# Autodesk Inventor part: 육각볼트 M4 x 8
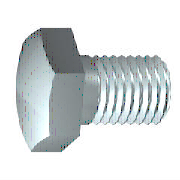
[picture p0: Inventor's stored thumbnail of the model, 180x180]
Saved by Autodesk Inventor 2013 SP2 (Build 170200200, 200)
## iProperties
Created: 2012-02
Part Number: 육각볼트 M4 x 8
Material: 강철, 연강
Description: 6각 머리 나사
Document SubType Name: Modeling
Standard: ISO 4017
Designer: mduedu
Standard Revision: Third edition 1999-08-15
Standards Organization: ISO
Language: ko-KR
Size Designation: M4 x 10
Categories: <MemberInstance><Categories><Category DisplayName="조임쇠" InternalName="e4da775c-781d-43d5-af7c-5136215cf5a6" Mnemonic="FSTN"><Category DisplayName="볼트" InternalN
Density: 7.86 g/cm^3
IsCustomPart: 0
Author: mduedu
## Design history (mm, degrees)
sketch "스케치1"
  geometry: L1 (0, 3.015)-(0, 2); L2 (1.75, 2)-(8, 2); L3 (8, 2)-(8, 0); L4 (8, 0)-(-0.4, 0); L5 (-2.08, 0)-(9.68, 0) reference; L6 (-0.4, 0)-(-0.4, 3.015); L7 (-0.4, 3.015)-(0, 3.015); L8 (1.75, 2)-(1.32, 2); L9 (1.32, 2)-(0, 2); L10 (0, -0.603)-(0, 3.618) reference
  constraints: 16 end point, 2 collinear, 2 perpendicular, 1 parallel
  dimensions: "d0" = 8 distance between parallel lines of L3 L1 (= NLG); "d1" = 6.25 distance from line of L2.start L3 (= GEL); "d2" = 4 diameter of L2 L4 (= GD); "d9" = 0.4001 distance between parallel lines of L6 L1 (computed from SD); "d10" = 6.03 diameter of L7 L4 (= SD2); "d13" = 0.42952 distance of L2.start L8.end (computed from GAL); "d14" = 4 diameter of L9 L4 (= BDM)
revolve "본체" sketch "스케치1" stored, may be unused: angle "d12" = 90 deg
sketch "스케치2"
  geometry: L1 (0, 4.041)-(3.5, 2.021); L2 (3.5, 2.021)-(3.5, -2.021); L3 (3.5, -2.021)-(0, -4.041); L4 (0, -4.041)-(-3.5, -2.021); L5 (-3.5, -2.021)-(-3.5, 2.021); L6 (-3.5, 2.021)-(0, 4.041); 2 further points
  constraints: 12 end point, 1 coincident, 1 vertical, 11 other
  dimensions: "d11" = 7 distance between parallel lines of L5 L2 (= SW)
extrude "머리" join sketch "스케치2" distance "d3" = 2.4 (= KOH - SD); taper "d4" = 0 deg
sketch "스케치4"
  geometry: L1 (-2.8, 3.5)-(-2.8, 4.041); L2 (-2.8, 4.041)-(-2.487, 4.041); L3 (-2.487, 4.041)-(-2.8, 3.5); L4 (-3.28, 0)-(0.08, 0) reference; L5 (-0.4, 4.041)-(-2.8, 4.041) reference; L6 (-2.8, 2.021)-(-2.8, 4.041) reference
  constraints: 6 end point, 2 collinear, 1 perpendicular, 1 vertical
  dimensions: "d5" = 30 deg angle of L3 L1 (= ANG1); "d19" = 7 diameter of L1.start L4 (= SW0)
revolve "모따기1" sketch "스케치4" stored, may be unused: angle "d21" = 90 deg
workplane "Work Plane1"
body "Solid1"
feature "스레드" dims "d15" = 6.25 (= GEL), "d16" = 0
chamfer "모따기2" distance "d6" = 0.42941 (= -0.5 x SPD + 0.5 x GD); stored, may be unused: second distance "d7" = 0.42952 (computed from GUL), angle "d55" = 45 deg
other parameters: "NLG" = 8 [user parameter; used in 1 equation term], "GD" = 4 (= NND) [user parameter; used in 2 equation terms], "BDM" = 4 (= NND) [user parameter; used in 1 equation term], "KOH" = 2.8 [user parameter; used in 1 equation term], "GEL" = 6.25 [user parameter; used in 2 equation terms], "SW" = 7 [user parameter; used in 2 equation terms], "SW0" = 7 (= SW) [user parameter; used in 1 equation term], "SPD" = 3.14117 (= NND - 1.2269 x PTC) [user parameter; used in 1 equation term], "SD2" = 6.03 [user parameter; used in 2 equation terms], "SD" = 0.4 [user parameter; used in 2 equation terms], "ANG1" = 30 deg [user parameter; used in 1 equation term], "GAL" = 0.42941 (= 0.61345 x PTC) [user parameter; used in 1 equation term], "GUL" = 0.42941 (= 0.61345 x PTC) [user parameter; used in 1 equation term], "d8" = 0, "RR" = 0.2 [user parameter], "d57" = 0, "d58" = 0, "TPU" = 14.28571 (computed from PTC) [user parameter], "GD1" = 3.14117 (= THREADDIA - 1.2269 x PTC) [user parameter], "THREADDIA" = 4 [user parameter; used in 1 equation term], "SDH" = 6.03 (= SD2) [user parameter], "SDHG" = 2.1 [user parameter], "TOA" = 30 deg [user parameter], "PTC" = 0.7 [user parameter; used in 5 equation terms], "NND" = 4 [user parameter; used in 3 equation terms], "E0" = 8.085 [user parameter]
